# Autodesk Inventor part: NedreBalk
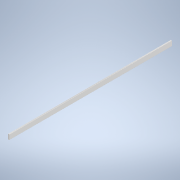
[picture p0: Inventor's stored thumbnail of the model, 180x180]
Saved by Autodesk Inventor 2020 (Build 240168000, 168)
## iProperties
Created: 2019-06
Part Number: NedreBalk
Material: Aluminum
Document SubType Name: Modeling
Designer: cl
Density: 2.7 g/cm^3
Appearance: Satin
Author: cl
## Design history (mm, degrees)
sketch "Sketch1"
  geometry: L1 (0, 0)-(7, 0); L2 (12, -5)-(12, -85); L3 (7, -90)-(0, -90); L4 (0, 0)-(0, -90); L5 (0, 0)-(-7, 0); L6 (-12, -5)-(-12, -85); L7 (-7, -90)-(0, -90); A1 r 5 centre (7, -5) between (12, -5) and (7, 0); A2 r 5 centre (7, -85) between (7, -90) and (12, -85); A3 r 5 centre (-7, -5) between (-7, 0) and (-12, -5); A4 r 5 centre (-7, -85) between (-12, -85) and (-7, -90); 4 further points
  constraints: 14 end point, 8 point on circle, 8 point on line, 8 symmetric about line, 4 centre point, 4 tangent, 2 perpendicular, 1 equal radius, 1 horizontal, 1 vertical, 2 other
  dimensions: "d0" = 12 distance of L1.start point (12, 0); "d1" = 90 distance of point (12, 0) point (12, -90); "d2" = 5 radius of A1
extrude "Extrusion1" new body sketch "Sketch1" distance "d3" = 2970 (computed from Dagbredd); taper "d4" = 0 deg
body "Solid1"
